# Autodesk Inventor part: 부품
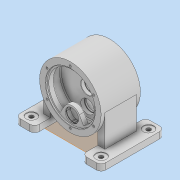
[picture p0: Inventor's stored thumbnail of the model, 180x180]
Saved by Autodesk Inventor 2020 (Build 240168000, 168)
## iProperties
Created: 2025-12
Part Number: 부품
Material: 일반
Document SubType Name: Modeling
Designer: PC2-06
Density: 1 g/cm^3
Appearance: 기본값
Author: PC2-06
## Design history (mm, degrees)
sketch "스케치1"
  geometry: L1 (0, 62)-(0, -62); L2 (0, 62)-(78, 62); L3 (78, 62)-(78, 57); L4 (78, 57)-(73, 57); L5 (73, 57)-(73, 43); L6 (76, 40)-(82, 40); L7 (85, 37)-(85, 11); L8 (82, 8)-(21, 8); L9 (21, 8)-(21, -3.4); L10 (20.4, -4)-(19, -4); L11 (19, -4)-(19, -8); L12 (19, -8)-(84, -8); L13 (87, -11)-(87, -37); L14 (84, -40)-(73, -40); L15 (73, -40)-(73, -57); L16 (73, -57)-(78, -57); L17 (78, -57)-(78, -62); L18 (78, -62)-(0, -62); L19 (78, 62)-(97, 62); L20 (97, 62)-(97, -62); L21 (97, -62)-(78, -62); L22 (76, 40)-(73, 40); L23 (73, 40)-(73, 43); A1 r 0.6 centre (20.4, -3.4) between (20.4, -4) and (21, -3.4); A2 r 3 centre (82, 37) between (85, 37) and (82, 40); A3 r 3 centre (82, 11) between (82, 8) and (85, 11); A4 r 3 centre (84, -11) between (87, -11) and (84, -8); A5 r 3 centre (84, -37) between (84, -40) and (87, -37); 7 further points
  constraints: 47 end point, 16 perpendicular, 14 point on line, 10 point on circle, 10 tangent, 5 centre point, 3 horizontal, 1 coincident, 1 collinear, 1 midpoint, 1 vertical
  dimensions: "d0" = 156 diameter of L3 L1; "d1" = 146 diameter of L5 L1; "d2" = 170 diameter of L7 L1; "d3" = 42 diameter of L9 L1; "d4" = 38 diameter of L11 L1; "d5" = 174 diameter of L13 L1; "d6" = 5 distance between parallel lines of L4 L2; "d7" = 22 distance between parallel lines of L2 L6; "d8" = 32 distance between parallel lines of L8 L6; "d9" = 32 distance between parallel lines of L14 L12; "d10" = 22 distance between parallel lines of L18 L14; "d11" = 5 distance between parallel lines of L18 L16; "d12" = 124 distance between parallel lines of L18 L2; "d13" = 12 distance between parallel lines of L10 L8; "d14" = 194 diameter of L20 L1; "d16" = 0.6 radius of A1 (derived)
revolve "회전1" sketch "스케치1" stored, may be unused: angle "d15" = 90 deg
sketch "스케치2"
  geometry: L1 (-21, -3.4)-(21, -3.4) reference; L2 (-21, 8)-(21, 8) reference; L3 (-19, -8)-(19, -8) reference; L4 (-19, -4)-(19, -4) reference; L5 (-82, 8)-(82, 8) reference; L6 (-31.5, 8)-(-31.5, -2.768); L7 (-32.1, -3.368)-(-33.5, -3.368); L8 (-33.5, -3.368)-(-33.5, -8); L9 (-52.5, 8)-(-52.5, -8); L10 (-84, -8)-(84, -8) reference; A1 r 0.6 centre (-32.1, -2.768) between (-32.1, -3.368) and (-31.5, -2.768); 1 further point
  constraints: 8 end point, 3 perpendicular, 3 point on line, 2 point on circle, 2 tangent, 1 centre point, 1 vertical
  dimensions: "d18" = 42 diameter of L6 L9; "d19" = 38 diameter of L8 L9; "d20" = 52.5 horizontal distance of L9.end point (0, 0); "d21" = 0.6 radius of A1
revolve "회전2" sketch "스케치2" stored, may be unused: angle "d22" = 90 deg
sketch "스케치3"
  geometry: L1 (23.383, -39)-(39.648, -67.172); L2 (-23.383, -39)-(-39.648, -67.172); C1 r 21 at (0, -52.5) reference; C2 r 21 at (0, -52.5); A1 r 27 centre (0, -52.5) between (23.383, -39) and (-23.383, -39); A2 r 78 centre (0, 0) between (39.648, -67.172) and (-39.648, -67.172) reference; 1 further point
  constraints: 4 end point, 4 point on circle, 2 centre point, 2 coincident, 2 tangent, 1 horizontal alignment
  dimensions: "d23" = 54 diameter of A1; "d24" = 42 diameter of C2; "d25" = 60 deg angle of L1 L2
extrude "돌출1" join sketch "스케치3" distance "d26" = 17; taper "d27" = 0 deg
fillet "모깎기1" dims "d30" = 3
node "작업 평면1"
sketch "스케치4"
  geometry: L1 (120, -100)-(90, -100); L2 (75, -85)-(75, 85); L3 (90, 100)-(120, 100); L4 (135, 85)-(135, -85); L5 (-90, -100)-(-120, -100); L6 (-135, -85)-(-135, 85); L7 (-120, 100)-(-90, 100); L8 (-75, 85)-(-75, -85); A1 r 15 centre (120, -85) between (120, -100) and (135, -85); A2 r 15 centre (120, 85) between (135, 85) and (120, 100); A3 r 15 centre (90, 85) between (90, 100) and (75, 85); A4 r 15 centre (90, -85) between (75, -85) and (90, -100); A5 r 15 centre (-90, -85) between (-90, -100) and (-75, -85); A6 r 15 centre (-120, -85) between (-135, -85) and (-120, -100); A7 r 15 centre (-120, 85) between (-120, 100) and (-135, 85); A8 r 15 centre (-90, 85) between (-75, 85) and (-90, 100); 3 further points
  constraints: 16 end point, 16 point on circle, 16 tangent, 8 centre point, 7 equal radius, 4 parallel, 2 horizontal, 2 horizontal alignment, 2 midpoint, 2 perpendicular
  dimensions: "d32" = 200 distance between parallel lines of L3 L1; "d33" = 60 distance between parallel lines of L2 L4; "d34" = 60 distance between parallel lines of L6 L8; "d35" = 15 radius of A1; "d36" = 200 distance between parallel lines of L7 L5; "d37" = 150 distance between parallel lines of L8 L2; "d38" = 75 distance from line of L2 point (0, 0)
extrude "돌출3" join sketch "스케치4" distance "d39" = 20; taper "d40" = 0 deg
sketch "스케치5"
  geometry: L1 (-75, -85)-(-75, 85) reference; L2 (-75, 50)-(-97, 50); L3 (-97, 50)-(-97, -50); L4 (-97, -50)-(-75, -50); L5 (-75, -50)-(-75, 50); L6 (75, 85)-(75, -85) reference; L7 (75, 50)-(97, 50); L8 (97, 50)-(97, -50); L9 (97, -50)-(75, -50); L10 (75, -50)-(75, 50); 5 further points
  constraints: 16 end point, 4 parallel, 2 horizontal, 2 horizontal alignment, 2 midpoint, 2 perpendicular, 2 point on line
  dimensions: "d41" = 22 distance of L4.end L3.end; "d42" = 100 distance of L3.end L2.end; "d43" = 22 distance between parallel lines of L8 L6; "d44" = 100 distance between parallel lines of L9 L7
extrude "돌출4" join sketch "스케치5" stored distance "d45" = 20; taper "d46" = 0 deg
sketch "스케치6"
  geometry: 5 further points
  constraints: 2 vertical alignment, 1 horizontal alignment
  dimensions: "d47" = 150 distance of point (-110, -75) point (-110, 75); "d48" = 150 distance of point (110, -75) point (110, 75); "d49" = 220 distance of point (110, -75) point (-110, -75); "d50" = 110 horizontal distance of point (110, -75) point (0, 0); "d51" = 75 vertical distance of point (0, 0) point (-110, 75)
hole "구멍1" sketch "스케치6" at (-110, 75), (-110, -75), (110, -75), (110, 75) diameter "d52" = 13.5; stored, may be unused: countersink angle "d56" = 82 deg, drill point angle "d58" = 118 deg; dims "d53" = 6, "d54" = 33, "d55" = 2, "d57" = 8
sketch "스케치7"
  geometry: L1 (-75, -120)-(-75, -100) reference; L2 (-75, -112)-(-36.6, -89.83); L3 (-189, -120)-(189, -120) reference; L4 (-75, -100)-(-75, -61.514) reference; A1 r 97 centre (0, 0) between (-36.6, -89.83) and (-75, -61.514) reference; 1 further point
  constraints: 2 end point, 1 point on circle, 1 point on line
  dimensions: "d59" = 8 distance from line of L3 L2.start; "d60" = 60 deg angle of L2 L4
sketch "스케치8"
  geometry: L1 (-31.5, 40)-(-72.802, 40) reference; L2 (-72.802, 57)-(-31.5, 57) reference; L3 (-40.5, 40)-(-66.914, 40) reference; L4 (-52.151, 57)-(-52.151, 40); L5 (-31.151, 57)-(-31.151, 53.95); L6 (-31.151, 53.95)-(-29.901, 53.95); L7 (-29.901, 53.95)-(-29.901, 52); L8 (-29.901, 52)-(-31.151, 52); L9 (-31.151, 52)-(-31.151, 40); L10 (-31.151, 57)-(-52.151, 57); L11 (-31.151, 40)-(-52.151, 40); 5 further points
  constraints: 16 end point, 5 point on line, 4 perpendicular, 3 midpoint, 1 collinear, 1 horizontal, 1 vertical, 1 vertical alignment
  dimensions: "d61" = 44.5 diameter of L7 L4; "d62" = 42 diameter of L5 L4; "d63" = 1.95 distance between parallel lines of L8 L6; "d64" = 12 distance between parallel lines of L1 L8
revolve "회전3" sketch "스케치8" stored, may be unused: angle "d65" = 90 deg
feature "리브1" dims "d66" = 1, "d67" = 12, "d68" = 0, "d69" = 0, "d70" = 1, "d71" = 1
sketch "스케치9"
  geometry: C1 r 85 at (0, 0); 3 further points
  constraints: 2 vertical alignment, 1 centre point, 1 coincident, 1 other
  dimensions: "d72" = 170 diameter of C1
hole "구멍2" sketch "스케치9" at (0, 85) diameter "d73" = 6.647; stored, may be unused: countersink angle "d77" = 82 deg, drill point angle "d79" = 118 deg; dims "d74" = 16, "d75" = 19.05, "d76" = 4.775, "d78" = 18
sketch "스케치10"
  geometry: C1 r 85 at (0, 0); 1 further point
  constraints: 1 centre point, 1 coincident
  dimensions: "d80" = 170 diameter of C1
chamfer "모따기1" distance "d84" = 1; stored, may be unused: second distance "d85" = 2, angle "d86" = 45 deg
node "솔리드1"
mirror "미러1"
pattern_circular "원형 패턴1" dims angle "d82" = 360 deg
node "투영된 루프1"
node "투영된 루프2"
feature "A9D066F2-1C7D-4E18-AEED-F7BC21143FA4" dims "d52" = 13.5, "d53" = 6, "d54" = 33, "d55" = 2, "d56" = 82 deg, "d57" = 8, "d58" = 118 deg
